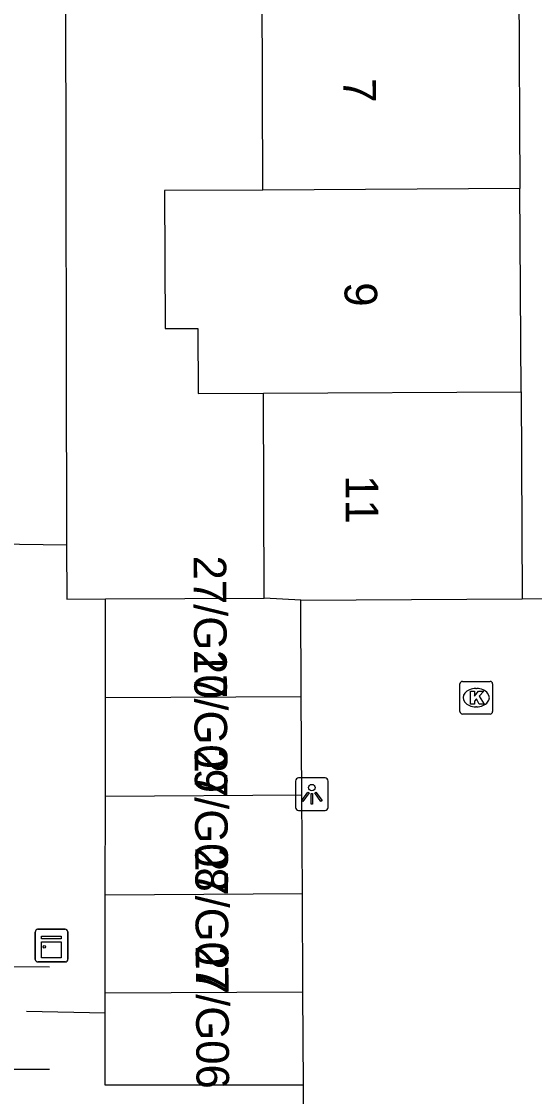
# Model space of a CAD drawing. Extents: x 160732 to 162105, y 387428 to 388479.
# Drawn here: x 161246.75 to 161262.48, y 387935.67 to 387968.6 of the extents above; entities that cross this region are included whole.
import ezdxf

# ---------------------------------------------------------------- set-up
doc = ezdxf.new("R2010")
doc.units = 0
for name, color, linetype in [('IMGEO_Hek', 7, 'Continuous'), ('IMGEO_Kast', 7, 'Continuous'), ('IMGEO_Kolk', 7, 'Continuous'), ('IMGEO_Lichtpunt', 7, 'Continuous'), ('IMGEO_Pand', 7, 'Continuous'), ('IMGEO_Pand_nummerreeks', 7, 'Continuous'), ('IMGEO_Rijbaan_lokaal_open', 7, 'Continuous'), ('IMGEO_Voetpad_open', 7, 'Continuous')]:
    doc.layers.add(name, color=color, linetype=linetype)

msp = doc.modelspace()

# ---------------------------------------------------------------- linework, layer by layer
at = {"layer": 'IMGEO_Hek'}
for points in [[(161247.615, 387939.625), (161245.221, 387939.638)], [(161246.908, 387938.278), (161249.32, 387938.233)], [(161245.226, 387936.499), (161247.615, 387936.5)]]:
    msp.add_lwpolyline(points, dxfattribs=at)
at = {"layer": 'IMGEO_Kast'}
for p, q in [((161247.248, 387940.788), (161248.089, 387940.788)), ((161248.089, 387940.788), (161247.248, 387940.788)), ((161247.173, 387939.863), (161247.173, 387940.704)), ((161247.173, 387940.704), (161247.173, 387939.863)), ((161248.173, 387940.713), (161248.173, 387939.872)), ((161248.173, 387939.872), (161248.173, 387940.713)), ((161248.098, 387939.788), (161247.257, 387939.788)), ((161247.257, 387939.788), (161248.098, 387939.788))]:
    msp.add_line(p, q, dxfattribs=at)
for points in [[(161247.368, 387940.578), (161247.968, 387940.578), (161247.968, 387940.493), (161247.368, 387940.493), (161247.368, 387940.578)], [(161247.368, 387940.403), (161247.968, 387940.403), (161247.968, 387939.914), (161247.368, 387939.914), (161247.368, 387940.403)]]:
    msp.add_lwpolyline(points, dxfattribs=at)
msp.add_circle((161247.452, 387940.252), 0.0377, dxfattribs=at)
for centre, start, end in [((161247.251, 387940.71), 92.4484, 184.2845), ((161247.251, 387940.71), 92.4484, 184.2845), ((161248.095, 387940.71), 2.4484, 94.2845), ((161248.095, 387940.71), 2.4484, 94.2845), ((161247.251, 387939.866), 182.4484, 274.2845), ((161247.251, 387939.866), 182.4484, 274.2845), ((161248.095, 387939.866), 272.4484, 4.2845), ((161248.095, 387939.866), 272.4484, 4.2845)]:
    msp.add_arc(centre, 0.0779, start, end, dxfattribs=at)
at = {"layer": 'IMGEO_Kolk'}
for p, q in [((161260.194, 387947.458), (161260.194, 387948.31)), ((161260.269, 387948.384), (161261.121, 387948.384)), ((161261.195, 387948.31), (161261.195, 387947.458)), ((161260.682, 387948.164), (161260.707, 387948.164)), ((161261.121, 387947.384), (161260.269, 387947.384)), ((161260.705, 387947.604), (161260.68, 387947.604))]:
    msp.add_line(p, q, dxfattribs=at)
for points in [[(161260.194, 387947.458), (161260.194, 387948.31)], [(161260.269, 387948.384), (161261.121, 387948.384)], [(161261.195, 387948.31), (161261.195, 387947.458)], [(161260.515, 387948.084), (161260.638, 387948.084), (161260.638, 387947.933), (161260.768, 387948.084), (161260.932, 387948.084), (161260.786, 387947.933), (161260.939, 387947.684), (161260.787, 387947.684), (161260.702, 387947.848), (161260.638, 387947.781), (161260.638, 387947.684), (161260.515, 387947.684), (161260.515, 387948.084)], [(161261.121, 387947.384), (161260.269, 387947.384)]]:
    msp.add_lwpolyline(points, dxfattribs=at)
for centre, start, end in [((161260.271, 387948.308), 91.552, 178.448), ((161260.271, 387948.308), 91.552, 178.448), ((161261.119, 387948.308), 1.552, 88.448), ((161261.119, 387948.308), 1.552, 88.448), ((161260.271, 387947.46), 181.552, 268.448), ((161260.271, 387947.46), 181.552, 268.448), ((161261.119, 387947.46), 271.552, 358.448), ((161261.119, 387947.46), 271.552, 358.448)]:
    msp.add_arc(centre, 0.0765, start, end, dxfattribs=at)
for centre, major_axis, ratio, start_param, end_param in [((161260.681, 387947.884), (-0.387, 0.002), 0.722429, 4.712389, 7.853982), ((161260.706, 387947.884), (-0.39, 0.002), 0.717154, 1.570796, 4.712389)]:
    msp.add_ellipse(centre, major_axis=major_axis, ratio=ratio, start_param=start_param, end_param=end_param, dxfattribs=at)
at = {"layer": 'IMGEO_Lichtpunt'}
for p, q in [((161255.156, 387945.33), (161255.156, 387944.523)), ((161255.156, 387945.33), (161255.156, 387944.523)), ((161256.058, 387945.425), (161255.25, 387945.425)), ((161256.058, 387945.425), (161255.25, 387945.425)), ((161256.152, 387944.523), (161256.152, 387945.33)), ((161256.152, 387944.523), (161256.152, 387945.33)), ((161255.25, 387944.429), (161256.058, 387944.429)), ((161255.25, 387944.429), (161256.058, 387944.429))]:
    msp.add_line(p, q, dxfattribs=at)
for points in [[(161255.53, 387944.994), (161255.569, 387944.966), (161255.381, 387944.704), (161255.343, 387944.731), (161255.53, 387944.994)], [(161255.632, 387944.946), (161255.679, 387944.946), (161255.679, 387944.624), (161255.632, 387944.624), (161255.632, 387944.946)], [(161255.742, 387944.966), (161255.78, 387944.993), (161255.967, 387944.731), (161255.928, 387944.703), (161255.742, 387944.966)]]:
    msp.add_lwpolyline(points, dxfattribs=at)
msp.add_circle((161255.655, 387945.128), 0.0994, dxfattribs=at)
for centre, start, end in [((161255.25, 387945.33), 90, 180), ((161255.25, 387945.33), 90, 180), ((161256.058, 387945.33), 0, 90), ((161256.058, 387945.33), 0, 90), ((161255.25, 387944.523), 180, 270), ((161255.25, 387944.523), 180, 270), ((161256.058, 387944.523), 270, 0), ((161256.058, 387944.523), 270, 360)]:
    msp.add_arc(centre, 0.0946, start, end, dxfattribs=at)
at = {"layer": 'IMGEO_Pand'}
for points in [[(161262.001, 387969.706), (161262.035, 387963.48)], [(161254.152, 387963.436), (161254.133, 387969.662)], [(161262.035, 387963.48), (161254.152, 387963.436)], [(161262.07, 387957.254), (161262.035, 387963.48)], [(161254.152, 387963.436), (161251.135, 387963.419), (161251.159, 387959.193), (161252.159, 387959.199), (161252.17, 387957.199), (161254.17, 387957.21)], [(161254.17, 387957.21), (161262.07, 387957.254)], [(161254.189, 387950.935), (161254.17, 387957.21)], [(161262.07, 387957.254), (161262.106, 387950.91)], [(161249.328, 387950.908), (161254.189, 387950.935)], [(161255.315, 387950.872), (161254.189, 387950.935)], [(161249.326, 387947.888), (161249.328, 387950.908)], [(161255.315, 387950.872), (161262.106, 387950.91)], [(161255.331, 387947.922), (161255.315, 387950.872)], [(161249.324, 387944.869), (161249.326, 387947.888)], [(161249.326, 387947.888), (161255.331, 387947.922)], [(161255.348, 387944.903), (161255.331, 387947.922)], [(161249.322, 387941.849), (161249.324, 387944.869)], [(161249.324, 387944.869), (161255.348, 387944.903)], [(161255.365, 387941.884), (161255.348, 387944.903)], [(161249.32, 387938.83), (161249.322, 387941.849)], [(161249.322, 387941.849), (161255.365, 387941.884)], [(161255.382, 387938.864), (161255.365, 387941.884)], [(161255.398, 387936.01), (161249.318, 387936.014), (161249.32, 387938.233), (161249.32, 387938.83)], [(161255.382, 387938.864), (161249.32, 387938.83)], [(161255.398, 387936.01), (161255.382, 387938.864)]]:
    msp.add_lwpolyline(points, dxfattribs=at)
at = {"layer": 'IMGEO_Rijbaan_lokaal_open'}
for points in [[(161262.106, 387950.91), (161265.944, 387950.957)], [(161255.406, 387932.376), (161255.398, 387936.01)]]:
    msp.add_lwpolyline(points, dxfattribs=at)
at = {"layer": 'IMGEO_Voetpad_open'}
for points in [[(161248.071, 387986.562), (161248.135, 387952.571)], [(161243.083, 387952.638), (161248.135, 387952.571)], [(161248.135, 387952.571), (161248.138, 387950.901), (161249.328, 387950.908)]]:
    msp.add_lwpolyline(points, dxfattribs=at)

# ---------------------------------------------------------------- texts
at = {"layer": 'IMGEO_Pand_nummerreeks'}
for s, rotation, p in [('7', 270.3191, (161256.621, 387966.859)), ('9', 270.3206, (161256.655, 387960.606)), ('11', 270.3191, (161256.688, 387954.697)), ('27/G10', 270.3203, (161252.027, 387952.235)), ('27/G09', 270.3203, (161252.043, 387949.348)), ('27/G08', 270.3203, (161252.06, 387946.322)), ('27/G07', 270.3203, (161252.077, 387943.306)), ('27/G06', 270.3203, (161252.094, 387940.287))]:
    msp.add_text(s, height=1, rotation=rotation, dxfattribs=at).set_placement(p)

doc.saveas('drawing.dxf')
